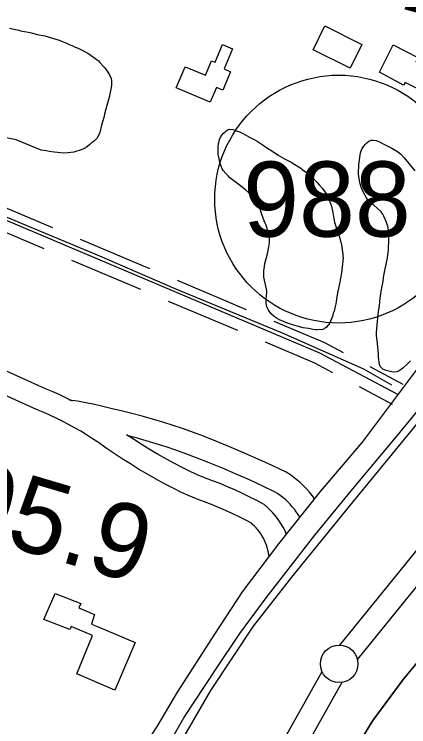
# Model space of a CAD drawing. Extents: x 3297735 to 3335592, y 670436 to 695807.
# Drawn here: x 3315202 to 3315727, y 691011 to 691960 of the extents above; entities that cross this region are included whole.
import ezdxf

# ---------------------------------------------------------------- set-up
doc = ezdxf.new("R2010")
doc.units = 0
for name, color, linetype in [('V-BLDG-OTLN', 7, 'Continuous'), ('V-BORW-LINE', 7, 'Continuous'), ('V-LEVE-TOET', 7, 'Continuous'), ('V-ROAD-CNTR', 7, 'Continuous'), ('V-ROAD-IDEN', 7, 'Continuous'), ('V-SITE-VEGE', 7, 'Continuous'), ('V-SURV-IDEN', 7, 'Continuous'), ('V-SURV-LINE', 7, 'Continuous'), ('V-TOPO-SHOR', 7, 'Continuous'), ('V-WETL-SWMP', 7, 'Continuous')]:
    doc.layers.add(name, color=color, linetype=linetype)

msp = doc.modelspace()

# ---------------------------------------------------------------- linework, layer by layer
at = {"layer": 'V-BLDG-OTLN'}
for points in [[(3315599.78, 691912.49), (3315615.52, 691944.08), (3315664.92, 691919.48), (3315649.18, 691887.88)], [(3315783.79, 691941.93), (3315839.44, 691913.52), (3315801.79, 691842.6), (3315787.88, 691849.79), (3315781.04, 691839.95), (3315722.67, 691869.06), (3315720.28, 691865.33), (3315688.38, 691882.44), (3315706.53, 691919.09), (3315739.45, 691902.32), (3315736.71, 691895.87), (3315755.37, 691886.28)], [(3315462.93, 691842.87), (3315417.73, 691861.86), (3315429.5, 691889.88), (3315456.71, 691878.44), (3315464.81, 691897.71), (3315469.28, 691895.83), (3315479.15, 691919.33), (3315492.65, 691913.66), (3315481.4, 691886.85), (3315490.04, 691883.22), (3315479.71, 691858.65), (3315471.07, 691862.26)], [(3315363.06, 691123.42), (3315335.97, 691059.95), (3315285.39, 691081.54), (3315306.31, 691132.46), (3315277.8, 691144.8), (3315276.08, 691140.39), (3315241.45, 691153.77), (3315256.53, 691188.4), (3315290.82, 691175.01), (3315288.08, 691169.24), (3315308.79, 691160.67), (3315304.67, 691147.77), (3315313.49, 691144)]]:
    msp.add_lwpolyline(points, close=True, dxfattribs=at)
at = {"layer": 'V-BORW-LINE'}
msp.add_spline([(3316995.19, 691930.46), (3317005.04, 692007.66), (3317000.73, 692060.53), (3316978.97, 692099.49), (3316906.19, 692141.1), (3316833.29, 692187.23), (3316697.41, 692287.63), (3316663.26, 692310.16), (3316619.56, 692296.15), (3316590.92, 692259.44), (3316565.01, 692210.53), (3316480.24, 692005.74), (3316389.23, 691825.19), (3316305.53, 691699.32), (3316276.48, 691659.41), (3316186.55, 691545.67), (3316036.76, 691382.05), (3315921.08, 691241.35), (3315848.08, 691140.02), (3315652.34, 690837.57), (3315431.18, 690420.67), (3315366.48, 690281.6), (3315351.93, 690233.43), (3315347.59, 690183.53), (3315387.16, 690117.36), (3315426.15, 690095.12), (3315473.6, 690094.31), (3315510.73, 690108.44), (3315542.49, 690128.45), (3315605.13, 690188.3), (3315659.03, 690264.36), (3315680.95, 690299.03), (3315904.66, 690642.19), (3316007.96, 690811.35), (3316078, 690936.85), (3316101.2, 690968.46), (3316112.23, 690877.46), (3316165.02, 690879.03), (3316235.46, 690925.63), (3316271.09, 690958.63), (3316327.12, 691033.63), (3316466.84, 691261.08), (3316567.99, 691464.66), (3316598.36, 691502.42), (3316633.55, 691520.69), (3316678.11, 691524.6), (3316723.77, 691458.6), (3316762.99, 691470.77), (3316787.64, 691500.01), (3316883.3, 691688.42), (3316909.39, 691731.24), (3316973.65, 691855.57), (3316995.19, 691930.46)], degree=3, dxfattribs=at)
at = {"layer": 'V-LEVE-TOET'}
for points in [[(3314907.14, 690085.76), (3314976.67, 690209.28), (3315030.35, 690306.7), (3315086.37, 690401.76), (3315161.64, 690534.99), (3315227.45, 690647.12), (3315287.89, 690759.28), (3315343.58, 690858.36), (3315397.56, 690945.38), (3315463.71, 691059.53), (3315520.37, 691145.19), (3315573.27, 691212.43), (3315648.73, 691305.41), (3315744.41, 691421.46), (3315825.62, 691528.84), (3315860.03, 691571.42)], [(3315783.34, 691151.2), (3315719.63, 691074.07), (3315679.52, 691019.54), (3315654.89, 690979.72)]]:
    msp.add_lwpolyline(points, dxfattribs=at)
at = {"layer": 'V-ROAD-CNTR'}
for points in [[(3315712.79, 691453.36), (3315608.86, 691508.69), (3314898.55, 691808.86), (3314375.54, 692027.75), (3313765.92, 692290.26), (3313109.25, 692578.04), (3312978.8, 692635.68)], [(3316100.75, 691990.41), (3316053.2, 691919.41), (3316015.67, 691864.87), (3315959.62, 691798.12), (3315900.1, 691716.26), (3315877.11, 691675.63), (3315741.18, 691491.25), (3315665.24, 691389.9), (3315609.31, 691324.4), (3315553.62, 691254.63), (3315505.24, 691190.8), (3315468.68, 691134.19), (3315418.8, 691057.34), (3315392.51, 691012.92), (3315356.12, 690957.01), (3315256.09, 690773.32), (3315147.69, 690573.87)], [(3315253.38, 691675.2), (3315161.27, 691714.12)], [(3315241.7, 691647.56), (3315149.59, 691686.49)], [(3315382.34, 691620.7), (3315290.23, 691659.63)], [(3315370.66, 691593.07), (3315278.55, 691631.99)], [(3315511.3, 691566.2), (3315419.18, 691605.13)], [(3315499.62, 691538.57), (3315407.51, 691577.5)], [(3315640.4, 691508.89), (3315615.32, 691522.25), (3315548.14, 691550.63)], [(3315279.47, 691444.71), (3315270.72, 691449.09), (3315261.73, 691453.34), (3315252.65, 691457.41), (3315243.79, 691461.17), (3315210.37, 691476.15), (3315176.66, 691490.97), (3315142.8, 691505.58), (3315106.28, 691520.78)], [(3315626.3, 691482.41), (3315602.4, 691495.13), (3315536.46, 691523)], [(3315266.07, 691417.87), (3315257.59, 691422.11), (3315249.17, 691426.09), (3315240.67, 691429.91), (3315231.8, 691433.66), (3315198.19, 691448.73), (3315164.68, 691463.47), (3315131.1, 691477.96), (3315108.39, 691487.41)], [(3315719.84, 691466.6), (3315675.7, 691490.09)], [(3315705.74, 691440.12), (3315661.61, 691463.61)], [(3315601.76, 691314.94), (3315598.6, 691319.19), (3315594.99, 691323.61), (3315591.19, 691327.86), (3315587.2, 691331.94), (3315583.04, 691335.84), (3315578.71, 691339.55), (3315574.22, 691343.07), (3315569.57, 691346.38), (3315564.23, 691349.84), (3315545.48, 691358.74), (3315527.43, 691367.02), (3315509.26, 691375.06), (3315491, 691382.87), (3315472.63, 691390.43), (3315454.11, 691397.77), (3315440.63, 691402.79), (3315427.1, 691407.57), (3315413.49, 691412.14), (3315399.82, 691416.49), (3315386.07, 691420.62), (3315372.26, 691424.53), (3315358.39, 691428.21), (3315344.47, 691431.67), (3315330.74, 691434.85), (3315319.93, 691437.57), (3315308.74, 691440.11), (3315297.5, 691442.39), (3315286.21, 691444.4), (3315275.05, 691446.12)], [(3315541.14, 691239.33), (3315540.53, 691243.03), (3315539.82, 691246.33), (3315538.94, 691249.59), (3315537.9, 691252.8), (3315536.7, 691255.96), (3315535.34, 691259.05), (3315533.83, 691262.07), (3315532.17, 691265.01), (3315530.36, 691267.86), (3315528.42, 691270.62), (3315526.34, 691273.28), (3315524.12, 691275.83), (3315521.78, 691278.27), (3315519.33, 691280.58), (3315517.7, 691281.97), (3315510.17, 691286.01), (3315501.27, 691290.55), (3315492.27, 691294.91), (3315483.19, 691299.09), (3315474.03, 691303.09), (3315464.8, 691306.89), (3315455.48, 691310.51), (3315445.66, 691314.1), (3315435.05, 691318.5), (3315424.44, 691323.14), (3315412.66, 691329.09), (3315401.24, 691335.1), (3315389.93, 691341.29), (3315378.71, 691347.67), (3315367.59, 691354.22), (3315356.59, 691360.96), (3315345.69, 691367.86), (3315334.91, 691374.95), (3315324.24, 691382.21), (3315313.96, 691389.46), (3315306.24, 691394.6), (3315298.37, 691399.6), (3315290.41, 691404.43), (3315282.34, 691409.1), (3315274.19, 691413.61), (3315265.8, 691418.01)], [(3315564.22, 691267.91), (3315562.51, 691271.8), (3315560.33, 691276.16), (3315557.92, 691280.42), (3315555.31, 691284.54), (3315552.5, 691288.53), (3315549.49, 691292.37), (3315546.29, 691296.06), (3315542.91, 691299.58), (3315539.36, 691302.93), (3315534.7, 691306.89), (3315524.08, 691312.59), (3315514.63, 691317.41), (3315505.09, 691322.03), (3315495.46, 691326.47), (3315485.75, 691330.7), (3315475.95, 691334.75), (3315466.07, 691338.58), (3315456.56, 691342.06), (3315446.81, 691346.1), (3315437.23, 691350.29), (3315426.42, 691355.76), (3315415.43, 691361.54), (3315404.53, 691367.5), (3315393.74, 691373.63), (3315383.04, 691379.94), (3315372.45, 691386.42), (3315361.96, 691393.07), (3315351.59, 691399.89), (3315351.49, 691399.95)], [(3315582.06, 691290.26), (3315579.99, 691293.61), (3315577.54, 691297.23), (3315574.93, 691300.74), (3315572.17, 691304.12), (3315569.26, 691307.38), (3315566.21, 691310.51), (3315563.01, 691313.5), (3315559.69, 691316.34), (3315556.25, 691319.03), (3315552.7, 691321.57), (3315549.58, 691323.59), (3315532.8, 691331.56), (3315515.1, 691339.67), (3315497.3, 691347.55), (3315479.39, 691355.2), (3315461.39, 691362.61), (3315443.35, 691369.76), (3315430.39, 691374.58), (3315417.32, 691379.21), (3315404.17, 691383.63), (3315390.96, 691387.83), (3315377.67, 691391.82), (3315364.33, 691395.6), (3315352.17, 691398.82)]]:
    msp.add_lwpolyline(points, dxfattribs=at)
at = {"layer": 'V-ROAD-IDEN'}
msp.add_circle((3315633.91, 691713.63), 165, dxfattribs=at)
msp.add_circle((3315633.91, 691713.63), 165, dxfattribs=at)
at = {"layer": 'V-SITE-VEGE'}
for points in [[(3315195.56, 691941.33), (3315205.87, 691939), (3315208.16, 691938.42), (3315210.45, 691937.55), (3315218.47, 691936.38), (3315224.77, 691934.92), (3315232.5, 691932.89), (3315242.81, 691930.85), (3315252.83, 691927.94), (3315261.71, 691925.05), (3315271.73, 691921.29), (3315275.16, 691919.55), (3315280.03, 691917.53), (3315282.89, 691916.09), (3315286.89, 691914.35), (3315299.77, 691908), (3315304.34, 691904.83), (3315311.2, 691899.94), (3315313.49, 691897.92), (3315315.77, 691895.33), (3315320.06, 691891.02), (3315322.06, 691888.72), (3315325.48, 691884.12), (3315328.61, 691878.95), (3315330.89, 691874.36), (3315331.45, 691871.2), (3315331.43, 691865.47), (3315330.55, 691859.74), (3315329.97, 691857.74), (3315329.39, 691853.73), (3315328.8, 691850.86), (3315327.35, 691846), (3315323.86, 691833.4), (3315322.12, 691826.81), (3315321.25, 691822.23), (3315318.35, 691812.21), (3315315.73, 691802.47), (3315312.26, 691794.74), (3315309.1, 691791.6), (3315307.09, 691789.89), (3315304.5, 691787.9), (3315302.78, 691786.18), (3315297.6, 691782.47), (3315293.3, 691780.2), (3315289.85, 691778.78), (3315283.83, 691776.79), (3315281.24, 691776.23), (3315273.21, 691775.11), (3315267.77, 691774.84), (3315259.75, 691775.44), (3315255.16, 691776.03), (3315248.57, 691777.2), (3315244.27, 691778.08), (3315237.69, 691778.96), (3315204.67, 691792.3), (3315182.43, 691796.82)], [(3315637.83, 691615.61), (3315635.21, 691601.31), (3315634.09, 691596.91), (3315632.79, 691590.86), (3315631.1, 691580.96), (3315630.54, 691576.75), (3315629.98, 691574.18), (3315629.05, 691570.7), (3315627.74, 691564.28), (3315626.81, 691561.54), (3315625.51, 691557.14), (3315624.4, 691554.03), (3315621.81, 691548.16), (3315620.15, 691545.78), (3315617.58, 691543.04), (3315615.92, 691541.58), (3315612.98, 691539.94), (3315605.09, 691539.42), (3315602.52, 691539.61), (3315600.14, 691539.99), (3315593.73, 691541.29), (3315586.58, 691542.42), (3315578.7, 691544.46), (3315575.4, 691545.21), (3315564.59, 691548.92), (3315555.06, 691552.99), (3315551.95, 691554.65), (3315547.93, 691557.41), (3315544.27, 691560.55), (3315541.35, 691564.22), (3315539.89, 691566.61), (3315538.25, 691570.29), (3315537.53, 691574.88), (3315537.36, 691576.9), (3315537.37, 691580.2), (3315537.93, 691584.96), (3315538.13, 691589), (3315538.14, 691591.57), (3315537.96, 691593.77), (3315535.98, 691601.85), (3315534.35, 691609.56), (3315534.19, 691614.51), (3315534.38, 691618.18), (3315534.95, 691623.86), (3315535.7, 691627.71), (3315539.23, 691640.91), (3315541.1, 691649.89), (3315541.48, 691652.64), (3315541.67, 691655.21), (3315541.68, 691659.61), (3315541.33, 691664.01), (3315540.61, 691668.23), (3315538.44, 691675.58), (3315537.17, 691678.88), (3315535.89, 691681.64), (3315534.8, 691684.58), (3315531.72, 691693.21), (3315529.36, 691700.56), (3315528.45, 691702.76), (3315527.17, 691705.33), (3315525.35, 691708.46), (3315522.79, 691712.14), (3315519.87, 691715.82), (3315516.4, 691719.31), (3315514.76, 691721.34), (3315509.82, 691725.76), (3315501.59, 691732.39), (3315489.15, 691741.79), (3315486.59, 691744.55), (3315483.48, 691747.68), (3315480.19, 691751.72), (3315478.92, 691753.75), (3315477.28, 691757.42), (3315476.19, 691760.55), (3315474.21, 691769.54), (3315473.67, 691773.58), (3315473.33, 691783.11), (3315473.9, 691787.7), (3315474.65, 691790.81), (3315475.39, 691793.38), (3315476.87, 691796.31), (3315478.35, 691798.87), (3315480.37, 691801.25), (3315482.21, 691802.71), (3315484.23, 691804.54), (3315486.26, 691805.63), (3315488.64, 691806.54), (3315492.86, 691806.34), (3315495.06, 691805.6), (3315499.27, 691804.12), (3315502.02, 691803.01), (3315508.06, 691800.06), (3315515.02, 691796.18), (3315517.77, 691794.88), (3315520.51, 691793.22), (3315525.28, 691790.63), (3315533.33, 691785.47), (3315536.62, 691783.26), (3315541.01, 691780.12), (3315543.39, 691778.65), (3315553.27, 691772.01)], [(3315729.68, 691498.44), (3315726, 691494.6), (3315719.55, 691488.57), (3315714.41, 691484.92), (3315711.28, 691483.83), (3315706.7, 691483.3), (3315700.65, 691484.6), (3315697.17, 691485.53), (3315694.97, 691486.27), (3315692.77, 691487.38), (3315690.58, 691489.22), (3315689.3, 691490.88), (3315688.39, 691493.27), (3315687.67, 691496.39), (3315687.5, 691500.05), (3315687.14, 691503.36), (3315687.15, 691507.03), (3315685.74, 691521.34), (3315684.31, 691532.54), (3315684.32, 691536.2), (3315685.28, 691546.65), (3315685.84, 691550.87), (3315686.04, 691555.09), (3315687.17, 691564.07), (3315687.92, 691568.66), (3315688.3, 691571.77), (3315689.25, 691581.68), (3315690.95, 691593.41), (3315692.07, 691600.01), (3315693, 691603.86), (3315693.75, 691609.17), (3315695.44, 691618.34), (3315698.8, 691635.2), (3315699.18, 691639.42), (3315700.12, 691645.84), (3315700.72, 691660.51), (3315700.74, 691665.65), (3315700.57, 691668.76), (3315700.21, 691672.25), (3315699.67, 691675.37), (3315698.95, 691678.31), (3315698.05, 691681.25), (3315697.14, 691683.82), (3315694.04, 691690.98), (3315692.77, 691693.56), (3315690.4, 691696.68), (3315685.09, 691701.66), (3315680.71, 691705.52), (3315677.96, 691707.73), (3315676.31, 691709.21), (3315672.48, 691713.26), (3315671.02, 691715.28), (3315666.64, 691723.36), (3315663.91, 691729.43), (3315662.46, 691734.02), (3315660.66, 691743.2), (3315660.31, 691747.23), (3315660.9, 691759.7), (3315663.16, 691775.29), (3315663.9, 691777.85), (3315665.02, 691780.97), (3315667.23, 691784.08), (3315669.44, 691786.64), (3315671.46, 691788.46), (3315674.22, 691790.66), (3315677.34, 691791.93), (3315679.91, 691792.29), (3315683.95, 691791.72), (3315688.34, 691789.87), (3315694.02, 691786.73), (3315696.03, 691785.81), (3315704.82, 691781.38), (3315706.83, 691780.08), (3315712.33, 691776.95), (3315714.89, 691774.55), (3315716.53, 691773.27), (3315720.55, 691769.21), (3315723.48, 691766.08), (3315735.53, 691751.18)], [(3315553.27, 691772.01), (3315562.79, 691766.84), (3315565.54, 691765.55), (3315570.85, 691762.59), (3315575.42, 691759.82), (3315583.48, 691754.66), (3315585.31, 691753.19), (3315588.6, 691750.97), (3315590.61, 691749.5), (3315593.72, 691746.92), (3315598.48, 691742.68), (3315605.42, 691735.69), (3315607.98, 691732.56), (3315611.81, 691728.15), (3315616.74, 691721.34), (3315618.02, 691719.32), (3315622.21, 691710.13), (3315622.93, 691707.74), (3315624.2, 691704.26), (3315626.19, 691695.99), (3315627.45, 691687.92), (3315627.99, 691685.53), (3315628.53, 691682.41), (3315629.26, 691680.39), (3315630.71, 691675.62), (3315634.16, 691665.7), (3315635.42, 691661.66), (3315635.97, 691659.27), (3315636.87, 691656.33), (3315637.6, 691652.85), (3315638.67, 691646.06), (3315639.39, 691640.37), (3315639.56, 691637.8), (3315639.92, 691635.41), (3315637.83, 691615.61)]]:
    msp.add_lwpolyline(points, dxfattribs=at)
at = {"layer": 'V-SURV-LINE'}
for points in [[(3315635.55, 691119.82), (3316225.87, 691847.2)], [(3316249.17, 691828.3), (3315658.85, 691100.93)], [(3315170.44, 690298.5), (3315611.76, 691084.78)], [(3315637.92, 691070.11), (3315196.6, 690283.83)]]:
    msp.add_lwpolyline(points, dxfattribs=at)
msp.add_circle((3315634.61, 691094.86), 25, dxfattribs=at)
at = {"layer": 'V-TOPO-SHOR'}
for points in [[(3315704.82, 691465.71), (3315667.37, 691487.39), (3315559.04, 691535.34), (3315416.19, 691594.19), (3315316.01, 691637.65), (3315176.13, 691695.74), (3315033.67, 691757.93), (3314929.03, 691802.15), (3314825.86, 691844.78)], [(3315197.57, 690618.44), (3315271.97, 690745.25), (3315351.62, 690888.78), (3315427.91, 691023.02), (3315470.87, 691088.26), (3315502.25, 691135.34), (3315537.35, 691182.78), (3315602.3, 691266.16), (3315652.68, 691327.66), (3315709.78, 691395.83), (3315746.35, 691440.66)]]:
    msp.add_lwpolyline(points, dxfattribs=at)
at = {"layer": 'V-WETL-SWMP'}
for p, q in [((3315719.63, 691074.07), (3315783.34, 691151.2)), ((3315679.53, 691019.54), (3315719.63, 691074.07)), ((3315654.9, 690979.71), (3315679.53, 691019.54))]:
    msp.add_line(p, q, dxfattribs=at)

# ---------------------------------------------------------------- texts
at = {"layer": 'V-ROAD-IDEN'}
msp.add_text('988', height=100, rotation=0.0583, dxfattribs=at).set_placement((3315506.8, 691663.5))
at = {"layer": 'V-SURV-IDEN'}
for s, rotation, p in [('3992+19.1', 345.10969, (3315348.71, 692065.36)), ('4001+95.9', 343.53027, (3314756.39, 691380.82))]:
    msp.add_text(s, height=100, rotation=rotation, dxfattribs=at).set_placement(p)

doc.saveas('drawing.dxf')
